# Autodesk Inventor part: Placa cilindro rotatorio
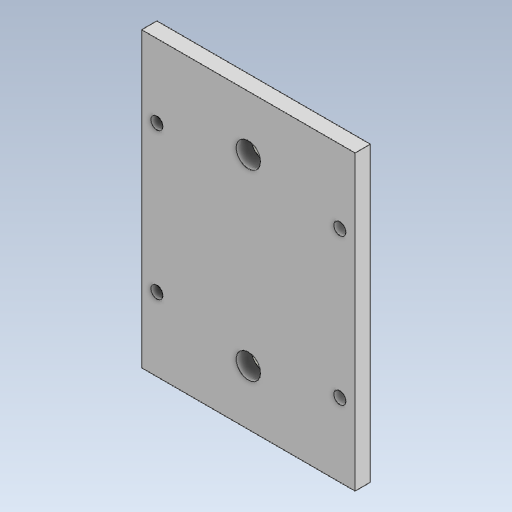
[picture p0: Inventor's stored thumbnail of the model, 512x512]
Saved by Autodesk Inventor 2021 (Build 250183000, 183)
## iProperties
Created: 2021-02
Part Number: Placa cilindro rotatorio
Material: Genérico
Document SubType Name: Modeling
Designer: ATOUZA
Density: 1 g/cm^3
Appearance: Valor por defecto
Author: ATOUZA
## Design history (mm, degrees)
node "Plano de trabajo1"
sketch "Boceto1"
  geometry: L1 (50, 9.5)-(50, 82.5) reference; L2 (0, 0)-(50, 0) reference; L3 (0, 9.5)-(0, 82.5) reference; L4 (0, 0)-(0, 9.45) reference; L5 (50, 0)-(50, 9.45) reference; L6 (0, 92)-(50, 92) reference; L7 (60, 94)-(-10, 94); L8 (-10, 94)-(-10, -2); L9 (-10, -2)-(60, -2); L10 (60, -2)-(60, 94); L11 (60, 94)-(-10, -2); L12 (-10, 94)-(60, -2); L13 (60, 46)-(-10, 46); L14 (25, -2)-(25, 46); L15 (25, 22)-(-10, 22); C1 r 4 at (25, 16) reference; C2 r 4 at (25, 76) reference; C3 r 3.323 at (25, 16) reference; C4 r 3.323 at (25, 76) reference; C5 r 3 at (25, 46) reference; C6 r 4 at (25, 16); C7 r 4 at (25, 76); C8 r 2 at (-5, 22); C9 r 2 at (-5, 70); C10 r 2 at (55, 22); C11 r 2 at (55, 70)
  constraints: 18 end point, 6 centre point, 6 midpoint, 3 perpendicular, 3 symmetric about line, 2 coincident, 2 concentric, 2 parallel, 2 point on line, 1 horizontal, 3 other
  dimensions: "d0" = 70 distance of L9.end L8.end; "d1" = 96 distance of L8.end L7.end; "d2" = 4 diameter of C8; "d3" = 5 distance from line of L8 C8.centre
extrude "Extrusión1" new body sketch "Boceto1" distance "d4" = 5; taper "d5" = 0 deg
node "Sólido1"
node "Referencia1"
node "Referencia2"
node "Referencia3"
node "Referencia4"
node "Referencia6"
node "Referencia7"
node "Referencia8"
node "Referencia9"
node "Referencia10"
node "Referencia11"
node "Referencia12"
